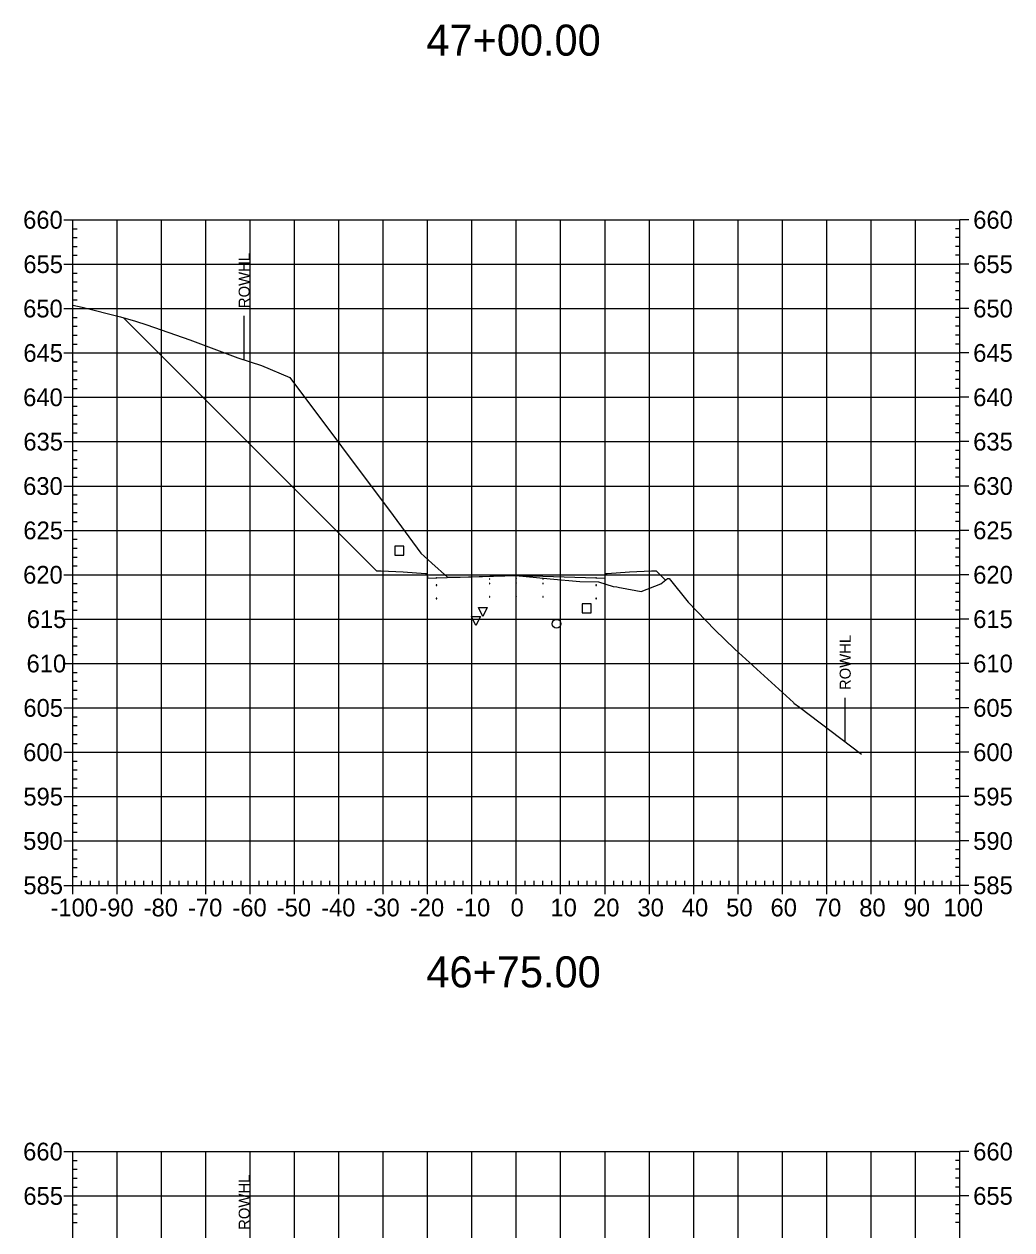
# Model space of a CAD drawing. Extents: x 708103 to 717568, y 374476 to 378707.
# Drawn here: x 712241 to 712463.7, y 377347 to 377618.7 of the extents above; entities that cross this region are included whole.
import ezdxf

# ---------------------------------------------------------------- set-up
doc = ezdxf.new("R2010")
doc.units = 0
for name, color, linetype in [('1', 7, 'Continuous'), ('10', 7, 'Continuous'), ('13', 7, 'Continuous'), ('14', 7, 'Continuous'), ('22', 7, 'Continuous'), ('4', 7, 'Continuous'), ('57', 7, 'Continuous'), ('Existing', 7, 'Continuous'), ('XS_Right_of_Way', 7, 'Continuous')]:
    doc.layers.add(name, color=color, linetype=linetype)

msp = doc.modelspace()

# ---------------------------------------------------------------- linework, layer by layer
for points in [[(712333.93, 377492.24), (712334.03, 377492.24), (712334.03, 377492.34), (712333.93, 377492.34)], [(712345.93, 377493.6), (712346.03, 377493.6), (712346.03, 377493.7), (712345.93, 377493.7)], [(712345.93, 377492.6), (712346.03, 377492.6), (712346.03, 377492.7), (712345.93, 377492.7)], [(712351.93, 377493.72), (712352.03, 377493.72), (712352.03, 377493.82), (712351.93, 377493.82)], [(712351.93, 377492.72), (712352.03, 377492.72), (712352.03, 377492.82), (712351.93, 377492.82)], [(712357.93, 377493.6), (712358.03, 377493.6), (712358.03, 377493.7), (712357.93, 377493.7)], [(712357.93, 377492.6), (712358.03, 377492.6), (712358.03, 377492.7), (712357.93, 377492.7)], [(712369.93, 377492.24), (712370.03, 377492.24), (712370.03, 377492.34), (712369.93, 377492.34)], [(712345.93, 377489.6), (712346.03, 377489.6), (712346.03, 377489.7), (712345.93, 377489.7)], [(712351.93, 377489.72), (712352.03, 377489.72), (712352.03, 377489.82), (712351.93, 377489.82)], [(712357.93, 377489.6), (712358.03, 377489.6), (712358.03, 377489.7), (712357.93, 377489.7)], [(712333.93, 377489.24), (712334.03, 377489.24), (712334.03, 377489.34), (712333.93, 377489.34)], [(712369.93, 377489.24), (712370.03, 377489.24), (712370.03, 377489.34), (712369.93, 377489.34)]]:
    msp.add_lwpolyline(points, close=True)
at = {"layer": '1'}
for points in [[(712344.45, 377485.25), (712343.45, 377487.25), (712345.45, 377487.25)], [(712342.88, 377483.21), (712341.88, 377485.21), (712343.88, 377485.21)]]:
    msp.add_lwpolyline(points, close=True, dxfattribs=at)
at = {"layer": '10'}
msp.add_lwpolyline([(712324.59, 377499.07), (712326.59, 377499.07), (712326.59, 377501.07), (712324.59, 377501.07)], close=True, dxfattribs=at)
at = {"layer": '13'}
msp.add_circle((712361.05, 377483.58), 1, dxfattribs=at)
at = {"layer": '14'}
for points in [[(712263.46, 377552.54), (712263.46, 377552.59), (712263.46, 377552.54), (712263.41, 377552.54), (712263.46, 377552.54), (712263.46, 377552.49), (712263.46, 377552.54), (712263.51, 377552.54)], [(712333.98, 377493.96), (712333.98, 377494.01), (712333.98, 377493.96), (712333.93, 377493.96), (712333.98, 377493.96), (712333.98, 377493.91), (712333.98, 377493.96), (712334.03, 377493.96)], [(712351.98, 377494.44), (712351.98, 377494.49), (712351.98, 377494.44), (712351.93, 377494.44), (712351.98, 377494.44), (712351.98, 377494.39), (712351.98, 377494.44), (712352.03, 377494.44)], [(712369.98, 377493.96), (712369.98, 377494.01), (712369.98, 377493.96), (712369.93, 377493.96), (712369.98, 377493.96), (712369.98, 377493.91), (712369.98, 377493.96), (712370.03, 377493.96)], [(712385.6, 377493.4), (712385.6, 377493.45), (712385.6, 377493.4), (712385.55, 377493.4), (712385.6, 377493.4), (712385.6, 377493.35), (712385.6, 377493.4), (712385.65, 377493.4)]]:
    msp.add_lwpolyline(points, dxfattribs=at)
at = {"layer": '22'}
msp.add_lwpolyline([(712263.46, 377552.54), (712320.48, 377495.52), (712321.48, 377495.48), (712326.48, 377495.28), (712331.48, 377494.88), (712331.9, 377494.88), (712331.98, 377493.88), (712333.98, 377493.96), (712345.98, 377494.32), (712351.98, 377494.44), (712357.98, 377494.32), (712369.98, 377493.96), (712371.98, 377493.88), (712372.07, 377494.88), (712372.48, 377494.88), (712377.48, 377495.28), (712382.48, 377495.48), (712383.48, 377495.52), (712385.6, 377493.4)], dxfattribs=at)
at = {"layer": '4'}
msp.add_lwpolyline([(712366.85, 377486.07), (712368.85, 377486.07), (712368.85, 377488.07), (712366.85, 377488.07)], close=True, dxfattribs=at)
at = {"layer": '57'}
for p, q in [((712249.98, 377574.63), (712251.98, 377574.63)), ((712251.98, 377574.63), (712451.98, 377574.63)), ((712251.98, 377424.63), (712251.98, 377574.63)), ((712251.98, 377424.63), (712251.98, 377574.63)), ((712261.98, 377424.63), (712261.98, 377574.63)), ((712271.98, 377424.63), (712271.98, 377574.63)), ((712281.98, 377424.63), (712281.98, 377574.63)), ((712291.98, 377424.63), (712291.98, 377574.63)), ((712301.98, 377424.63), (712301.98, 377574.63)), ((712311.98, 377424.63), (712311.98, 377574.63)), ((712321.98, 377424.63), (712321.98, 377574.63)), ((712331.98, 377424.63), (712331.98, 377574.63)), ((712341.98, 377424.63), (712341.98, 377574.63)), ((712351.98, 377424.63), (712351.98, 377574.63)), ((712361.98, 377424.63), (712361.98, 377574.63)), ((712371.98, 377424.63), (712371.98, 377574.63)), ((712381.98, 377424.63), (712381.98, 377574.63)), ((712391.98, 377424.63), (712391.98, 377574.63)), ((712401.98, 377424.63), (712401.98, 377574.63)), ((712411.98, 377424.63), (712411.98, 377574.63)), ((712421.98, 377424.63), (712421.98, 377574.63)), ((712431.98, 377424.63), (712431.98, 377574.63)), ((712441.98, 377424.63), (712441.98, 377574.63)), ((712451.98, 377424.63), (712451.98, 377574.63)), ((712451.98, 377424.63), (712451.98, 377574.63)), ((712453.98, 377574.63), (712451.98, 377574.63)), ((712251.98, 377572.63), (712252.98, 377572.63)), ((712451.98, 377572.63), (712450.98, 377572.63)), ((712251.98, 377570.63), (712252.98, 377570.63)), ((712251.98, 377568.63), (712252.98, 377568.63)), ((712451.98, 377570.63), (712450.98, 377570.63)), ((712451.98, 377568.63), (712450.98, 377568.63)), ((712251.98, 377566.63), (712252.98, 377566.63)), ((712451.98, 377566.63), (712450.98, 377566.63)), ((712249.98, 377564.63), (712251.98, 377564.63)), ((712251.98, 377564.63), (712451.98, 377564.63)), ((712453.98, 377564.63), (712451.98, 377564.63)), ((712251.98, 377562.63), (712252.98, 377562.63)), ((712251.98, 377560.63), (712252.98, 377560.63)), ((712451.98, 377562.63), (712450.98, 377562.63)), ((712451.98, 377560.63), (712450.98, 377560.63)), ((712251.98, 377558.63), (712252.98, 377558.63)), ((712451.98, 377558.63), (712450.98, 377558.63)), ((712251.98, 377556.63), (712252.98, 377556.63)), ((712451.98, 377556.63), (712450.98, 377556.63)), ((712249.98, 377554.63), (712251.98, 377554.63)), ((712251.98, 377554.63), (712451.98, 377554.63)), ((712251.98, 377552.63), (712252.98, 377552.63)), ((712451.98, 377552.63), (712450.98, 377552.63)), ((712453.98, 377554.63), (712451.98, 377554.63)), ((712251.98, 377550.63), (712252.98, 377550.63)), ((712451.98, 377550.63), (712450.98, 377550.63)), ((712251.98, 377548.63), (712252.98, 377548.63)), ((712251.98, 377546.63), (712252.98, 377546.63)), ((712451.98, 377548.63), (712450.98, 377548.63)), ((712451.98, 377546.63), (712450.98, 377546.63)), ((712249.98, 377544.63), (712251.98, 377544.63)), ((712251.98, 377544.63), (712451.98, 377544.63)), ((712453.98, 377544.63), (712451.98, 377544.63)), ((712251.98, 377542.63), (712252.98, 377542.63)), ((712451.98, 377542.63), (712450.98, 377542.63)), ((712251.98, 377540.63), (712252.98, 377540.63)), ((712251.98, 377538.63), (712252.98, 377538.63)), ((712451.98, 377540.63), (712450.98, 377540.63)), ((712451.98, 377538.63), (712450.98, 377538.63)), ((712251.98, 377536.63), (712252.98, 377536.63)), ((712451.98, 377536.63), (712450.98, 377536.63)), ((712249.98, 377534.63), (712251.98, 377534.63)), ((712251.98, 377534.63), (712451.98, 377534.63)), ((712453.98, 377534.63), (712451.98, 377534.63)), ((712251.98, 377532.63), (712252.98, 377532.63)), ((712251.98, 377530.63), (712252.98, 377530.63)), ((712451.98, 377532.63), (712450.98, 377532.63)), ((712451.98, 377530.63), (712450.98, 377530.63)), ((712251.98, 377528.63), (712252.98, 377528.63)), ((712451.98, 377528.63), (712450.98, 377528.63)), ((712251.98, 377526.63), (712252.98, 377526.63)), ((712451.98, 377526.63), (712450.98, 377526.63)), ((712249.98, 377524.63), (712251.98, 377524.63)), ((712251.98, 377524.63), (712451.98, 377524.63)), ((712251.98, 377522.63), (712252.98, 377522.63)), ((712451.98, 377522.63), (712450.98, 377522.63)), ((712453.98, 377524.63), (712451.98, 377524.63)), ((712251.98, 377520.63), (712252.98, 377520.63)), ((712451.98, 377520.63), (712450.98, 377520.63)), ((712251.98, 377518.63), (712252.98, 377518.63)), ((712451.98, 377518.63), (712450.98, 377518.63)), ((712249.98, 377514.63), (712251.98, 377514.63)), ((712251.98, 377516.63), (712252.98, 377516.63)), ((712251.98, 377514.63), (712451.98, 377514.63)), ((712451.98, 377516.63), (712450.98, 377516.63)), ((712453.98, 377514.63), (712451.98, 377514.63)), ((712251.98, 377512.63), (712252.98, 377512.63)), ((712451.98, 377512.63), (712450.98, 377512.63)), ((712251.98, 377510.63), (712252.98, 377510.63)), ((712251.98, 377508.63), (712252.98, 377508.63)), ((712451.98, 377510.63), (712450.98, 377510.63)), ((712451.98, 377508.63), (712450.98, 377508.63)), ((712251.98, 377506.63), (712252.98, 377506.63)), ((712451.98, 377506.63), (712450.98, 377506.63)), ((712249.98, 377504.63), (712251.98, 377504.63)), ((712251.98, 377504.63), (712451.98, 377504.63)), ((712453.98, 377504.63), (712451.98, 377504.63)), ((712251.98, 377502.63), (712252.98, 377502.63)), ((712251.98, 377500.63), (712252.98, 377500.63)), ((712451.98, 377502.63), (712450.98, 377502.63)), ((712451.98, 377500.63), (712450.98, 377500.63)), ((712251.98, 377498.63), (712252.98, 377498.63)), ((712451.98, 377498.63), (712450.98, 377498.63)), ((712251.98, 377496.63), (712252.98, 377496.63)), ((712451.98, 377496.63), (712450.98, 377496.63)), ((712249.98, 377494.63), (712251.98, 377494.63)), ((712251.98, 377494.63), (712451.98, 377494.63)), ((712251.98, 377492.63), (712252.98, 377492.63)), ((712451.98, 377492.63), (712450.98, 377492.63)), ((712453.98, 377494.63), (712451.98, 377494.63)), ((712251.98, 377490.63), (712252.98, 377490.63)), ((712451.98, 377490.63), (712450.98, 377490.63)), ((712251.98, 377488.63), (712252.98, 377488.63)), ((712451.98, 377488.63), (712450.98, 377488.63)), ((712249.98, 377484.63), (712251.98, 377484.63)), ((712251.98, 377486.63), (712252.98, 377486.63)), ((712251.98, 377484.63), (712451.98, 377484.63)), ((712451.98, 377486.63), (712450.98, 377486.63)), ((712453.98, 377484.63), (712451.98, 377484.63)), ((712251.98, 377482.63), (712252.98, 377482.63)), ((712451.98, 377482.63), (712450.98, 377482.63)), ((712251.98, 377480.63), (712252.98, 377480.63)), ((712251.98, 377478.63), (712252.98, 377478.63)), ((712451.98, 377480.63), (712450.98, 377480.63)), ((712451.98, 377478.63), (712450.98, 377478.63)), ((712251.98, 377476.63), (712252.98, 377476.63)), ((712451.98, 377476.63), (712450.98, 377476.63)), ((712249.98, 377474.63), (712251.98, 377474.63)), ((712251.98, 377474.63), (712451.98, 377474.63)), ((712453.98, 377474.63), (712451.98, 377474.63)), ((712251.98, 377472.63), (712252.98, 377472.63)), ((712251.98, 377470.63), (712252.98, 377470.63)), ((712451.98, 377472.63), (712450.98, 377472.63)), ((712451.98, 377470.63), (712450.98, 377470.63)), ((712251.98, 377468.63), (712252.98, 377468.63)), ((712451.98, 377468.63), (712450.98, 377468.63)), ((712251.98, 377466.63), (712252.98, 377466.63)), ((712451.98, 377466.63), (712450.98, 377466.63)), ((712249.98, 377464.63), (712251.98, 377464.63)), ((712251.98, 377464.63), (712451.98, 377464.63)), ((712251.98, 377462.63), (712252.98, 377462.63)), ((712451.98, 377462.63), (712450.98, 377462.63)), ((712453.98, 377464.63), (712451.98, 377464.63)), ((712251.98, 377460.63), (712252.98, 377460.63)), ((712451.98, 377460.63), (712450.98, 377460.63)), ((712251.98, 377458.63), (712252.98, 377458.63)), ((712451.98, 377458.63), (712450.98, 377458.63)), ((712249.98, 377454.63), (712251.98, 377454.63)), ((712251.98, 377456.63), (712252.98, 377456.63)), ((712251.98, 377454.63), (712451.98, 377454.63)), ((712451.98, 377456.63), (712450.98, 377456.63)), ((712453.98, 377454.63), (712451.98, 377454.63)), ((712251.98, 377452.63), (712252.98, 377452.63)), ((712451.98, 377452.63), (712450.98, 377452.63)), ((712251.98, 377450.63), (712252.98, 377450.63)), ((712451.98, 377450.63), (712450.98, 377450.63)), ((712251.98, 377448.63), (712252.98, 377448.63)), ((712251.98, 377446.63), (712252.98, 377446.63)), ((712451.98, 377448.63), (712450.98, 377448.63)), ((712451.98, 377446.63), (712450.98, 377446.63)), ((712249.98, 377444.63), (712251.98, 377444.63)), ((712251.98, 377444.63), (712451.98, 377444.63)), ((712453.98, 377444.63), (712451.98, 377444.63)), ((712251.98, 377442.63), (712252.98, 377442.63)), ((712251.98, 377440.63), (712252.98, 377440.63)), ((712451.98, 377442.63), (712450.98, 377442.63)), ((712451.98, 377440.63), (712450.98, 377440.63)), ((712251.98, 377438.63), (712252.98, 377438.63)), ((712451.98, 377438.63), (712450.98, 377438.63)), ((712251.98, 377436.63), (712252.98, 377436.63)), ((712451.98, 377436.63), (712450.98, 377436.63)), ((712249.98, 377434.63), (712251.98, 377434.63)), ((712251.98, 377434.63), (712451.98, 377434.63)), ((712251.98, 377432.63), (712252.98, 377432.63)), ((712451.98, 377432.63), (712450.98, 377432.63)), ((712453.98, 377434.63), (712451.98, 377434.63)), ((712251.98, 377430.63), (712252.98, 377430.63)), ((712451.98, 377430.63), (712450.98, 377430.63)), ((712251.98, 377428.63), (712252.98, 377428.63)), ((712451.98, 377428.63), (712450.98, 377428.63)), ((712249.98, 377424.63), (712251.98, 377424.63)), ((712251.98, 377426.63), (712252.98, 377426.63)), ((712251.98, 377424.63), (712451.98, 377424.63)), ((712251.98, 377424.63), (712451.98, 377424.63)), ((712251.98, 377422.63), (712251.98, 377424.63)), ((712253.98, 377424.63), (712253.98, 377425.63)), ((712255.98, 377424.63), (712255.98, 377425.63)), ((712257.98, 377424.63), (712257.98, 377425.63)), ((712259.98, 377424.63), (712259.98, 377425.63)), ((712261.98, 377422.63), (712261.98, 377424.63)), ((712263.98, 377424.63), (712263.98, 377425.63)), ((712265.98, 377424.63), (712265.98, 377425.63)), ((712267.98, 377424.63), (712267.98, 377425.63)), ((712269.98, 377424.63), (712269.98, 377425.63)), ((712271.98, 377422.63), (712271.98, 377424.63)), ((712273.98, 377424.63), (712273.98, 377425.63)), ((712275.98, 377424.63), (712275.98, 377425.63)), ((712277.98, 377424.63), (712277.98, 377425.63)), ((712279.98, 377424.63), (712279.98, 377425.63)), ((712281.98, 377422.63), (712281.98, 377424.63)), ((712283.98, 377424.63), (712283.98, 377425.63)), ((712285.98, 377424.63), (712285.98, 377425.63)), ((712287.98, 377424.63), (712287.98, 377425.63)), ((712289.98, 377424.63), (712289.98, 377425.63)), ((712291.98, 377422.63), (712291.98, 377424.63)), ((712293.98, 377424.63), (712293.98, 377425.63)), ((712295.98, 377424.63), (712295.98, 377425.63)), ((712297.98, 377424.63), (712297.98, 377425.63)), ((712299.98, 377424.63), (712299.98, 377425.63)), ((712301.98, 377422.63), (712301.98, 377424.63)), ((712303.98, 377424.63), (712303.98, 377425.63)), ((712305.98, 377424.63), (712305.98, 377425.63)), ((712307.98, 377424.63), (712307.98, 377425.63)), ((712309.98, 377424.63), (712309.98, 377425.63)), ((712311.98, 377422.63), (712311.98, 377424.63)), ((712313.98, 377424.63), (712313.98, 377425.63)), ((712315.98, 377424.63), (712315.98, 377425.63)), ((712317.98, 377424.63), (712317.98, 377425.63)), ((712319.98, 377424.63), (712319.98, 377425.63)), ((712321.98, 377422.63), (712321.98, 377424.63)), ((712323.98, 377424.63), (712323.98, 377425.63)), ((712325.98, 377424.63), (712325.98, 377425.63)), ((712327.98, 377424.63), (712327.98, 377425.63)), ((712329.98, 377424.63), (712329.98, 377425.63)), ((712331.98, 377422.63), (712331.98, 377424.63)), ((712333.98, 377424.63), (712333.98, 377425.63)), ((712335.98, 377424.63), (712335.98, 377425.63)), ((712337.98, 377424.63), (712337.98, 377425.63)), ((712339.98, 377424.63), (712339.98, 377425.63)), ((712341.98, 377422.63), (712341.98, 377424.63)), ((712343.98, 377424.63), (712343.98, 377425.63)), ((712345.98, 377424.63), (712345.98, 377425.63)), ((712347.98, 377424.63), (712347.98, 377425.63)), ((712349.98, 377424.63), (712349.98, 377425.63)), ((712351.98, 377422.63), (712351.98, 377424.63)), ((712353.98, 377424.63), (712353.98, 377425.63)), ((712355.98, 377424.63), (712355.98, 377425.63)), ((712357.98, 377424.63), (712357.98, 377425.63)), ((712359.98, 377424.63), (712359.98, 377425.63)), ((712361.98, 377422.63), (712361.98, 377424.63)), ((712363.98, 377424.63), (712363.98, 377425.63)), ((712365.98, 377424.63), (712365.98, 377425.63)), ((712367.98, 377424.63), (712367.98, 377425.63)), ((712369.98, 377424.63), (712369.98, 377425.63)), ((712371.98, 377422.63), (712371.98, 377424.63)), ((712373.98, 377424.63), (712373.98, 377425.63)), ((712375.98, 377424.63), (712375.98, 377425.63)), ((712377.98, 377424.63), (712377.98, 377425.63)), ((712379.98, 377424.63), (712379.98, 377425.63)), ((712381.98, 377422.63), (712381.98, 377424.63)), ((712383.98, 377424.63), (712383.98, 377425.63)), ((712385.98, 377424.63), (712385.98, 377425.63)), ((712387.98, 377424.63), (712387.98, 377425.63)), ((712389.98, 377424.63), (712389.98, 377425.63)), ((712391.98, 377422.63), (712391.98, 377424.63)), ((712393.98, 377424.63), (712393.98, 377425.63)), ((712395.98, 377424.63), (712395.98, 377425.63)), ((712397.98, 377424.63), (712397.98, 377425.63)), ((712399.98, 377424.63), (712399.98, 377425.63)), ((712401.98, 377422.63), (712401.98, 377424.63)), ((712403.98, 377424.63), (712403.98, 377425.63)), ((712405.98, 377424.63), (712405.98, 377425.63)), ((712407.98, 377424.63), (712407.98, 377425.63)), ((712409.98, 377424.63), (712409.98, 377425.63)), ((712411.98, 377422.63), (712411.98, 377424.63)), ((712413.98, 377424.63), (712413.98, 377425.63)), ((712415.98, 377424.63), (712415.98, 377425.63)), ((712417.98, 377424.63), (712417.98, 377425.63)), ((712419.98, 377424.63), (712419.98, 377425.63)), ((712421.98, 377422.63), (712421.98, 377424.63)), ((712423.98, 377424.63), (712423.98, 377425.63)), ((712425.98, 377424.63), (712425.98, 377425.63)), ((712427.98, 377424.63), (712427.98, 377425.63)), ((712429.98, 377424.63), (712429.98, 377425.63)), ((712431.98, 377422.63), (712431.98, 377424.63)), ((712433.98, 377424.63), (712433.98, 377425.63)), ((712435.98, 377424.63), (712435.98, 377425.63)), ((712437.98, 377424.63), (712437.98, 377425.63)), ((712439.98, 377424.63), (712439.98, 377425.63)), ((712441.98, 377422.63), (712441.98, 377424.63)), ((712443.98, 377424.63), (712443.98, 377425.63)), ((712445.98, 377424.63), (712445.98, 377425.63)), ((712447.98, 377424.63), (712447.98, 377425.63)), ((712449.98, 377424.63), (712449.98, 377425.63)), ((712451.98, 377426.63), (712450.98, 377426.63)), ((712451.98, 377422.63), (712451.98, 377424.63)), ((712453.98, 377424.63), (712451.98, 377424.63)), ((712249.98, 377364.63), (712251.98, 377364.63)), ((712251.98, 377364.63), (712451.98, 377364.63)), ((712251.98, 377224.63), (712251.98, 377364.63)), ((712251.98, 377224.63), (712251.98, 377364.63)), ((712261.98, 377224.63), (712261.98, 377364.63)), ((712271.98, 377224.63), (712271.98, 377364.63)), ((712281.98, 377224.63), (712281.98, 377364.63)), ((712291.98, 377224.63), (712291.98, 377364.63)), ((712301.98, 377224.63), (712301.98, 377364.63)), ((712311.98, 377224.63), (712311.98, 377364.63)), ((712321.98, 377224.63), (712321.98, 377364.63)), ((712331.98, 377224.63), (712331.98, 377364.63)), ((712341.98, 377224.63), (712341.98, 377364.63)), ((712351.98, 377224.63), (712351.98, 377364.63)), ((712361.98, 377224.63), (712361.98, 377364.63)), ((712371.98, 377224.63), (712371.98, 377364.63)), ((712381.98, 377224.63), (712381.98, 377364.63)), ((712391.98, 377224.63), (712391.98, 377364.63)), ((712401.98, 377224.63), (712401.98, 377364.63)), ((712411.98, 377224.63), (712411.98, 377364.63)), ((712421.98, 377224.63), (712421.98, 377364.63)), ((712431.98, 377224.63), (712431.98, 377364.63)), ((712441.98, 377224.63), (712441.98, 377364.63)), ((712451.98, 377224.63), (712451.98, 377364.63)), ((712451.98, 377224.63), (712451.98, 377364.63)), ((712453.98, 377364.63), (712451.98, 377364.63)), ((712251.98, 377362.63), (712252.98, 377362.63)), ((712451.98, 377362.63), (712450.98, 377362.63)), ((712251.98, 377360.63), (712252.98, 377360.63)), ((712451.98, 377360.63), (712450.98, 377360.63)), ((712251.98, 377358.63), (712252.98, 377358.63)), ((712251.98, 377356.63), (712252.98, 377356.63)), ((712451.98, 377358.63), (712450.98, 377358.63)), ((712451.98, 377356.63), (712450.98, 377356.63)), ((712249.98, 377354.63), (712251.98, 377354.63)), ((712251.98, 377354.63), (712451.98, 377354.63)), ((712453.98, 377354.63), (712451.98, 377354.63)), ((712251.98, 377352.63), (712252.98, 377352.63)), ((712451.98, 377352.63), (712450.98, 377352.63)), ((712251.98, 377350.63), (712252.98, 377350.63)), ((712251.98, 377348.63), (712252.98, 377348.63)), ((712451.98, 377350.63), (712450.98, 377350.63)), ((712451.98, 377348.63), (712450.98, 377348.63))]:
    msp.add_line(p, q, dxfattribs=at)
at = {"layer": 'Existing'}
msp.add_lwpolyline([(712251.98, 377555.43), (712254.12, 377554.91), (712262.73, 377552.74), (712266.16, 377551.8), (712268.72, 377550.99), (712278.4, 377547.58), (712289.18, 377543.56), (712294.55, 377541.78), (712300.9, 377539.06), (712324.19, 377507.95), (712330.45, 377499.51), (712332.97, 377497.22), (712336.44, 377494.1), (712339.34, 377494.11), (712351.9, 377494.45), (712359.62, 377493.7), (712366.27, 377493.11), (712370.53, 377493), (712373.84, 377491.95), (712374.68, 377491.89), (712375.22, 377491.73), (712375.66, 377491.65), (712380.16, 377490.87), (712384.57, 377492.56), (712386.05, 377493.76), (712386.42, 377493.82), (712390.75, 377488.42), (712396.72, 377482.23), (712401.25, 377477.87), (712414.44, 377465.83), (712414.56, 377465.71), (712415.81, 377464.76), (712429.82, 377454.18)], dxfattribs=at)
at = {"layer": 'XS_Right_of_Way'}
for p, q in [((712290.57, 377552.96), (712290.57, 377542.96)), ((712426.05, 377466.89), (712426.05, 377456.89))]:
    msp.add_line(p, q, dxfattribs=at)

# ---------------------------------------------------------------- texts
at = {"layer": '1'}
for s, p in [('47+00.00', (712331.71, 377611.63)), ('46+75.00', (712331.71, 377401.63))]:
    msp.add_text(s, height=7, dxfattribs=at).set_placement(p)
at = {"layer": '14'}
for p in [(712321.45, 377495.43), (712382.45, 377495.43), (712321.45, 377494.76), (712326.45, 377494.56), (712377.45, 377494.56), (712382.45, 377494.76)]:
    msp.add_text('+', height=0.1, dxfattribs=at).set_placement(p)
at = {"layer": '57'}
for s, p in [('660', (712240.81, 377572.63)), ('660', (712454.98, 377572.63)), ('655', (712240.86, 377562.63)), ('655', (712454.98, 377562.63)), ('650', (712240.81, 377552.63)), ('650', (712454.98, 377552.63)), ('645', (712240.86, 377542.63)), ('645', (712454.98, 377542.63)), ('640', (712240.81, 377532.63)), ('640', (712454.98, 377532.63)), ('635', (712240.86, 377522.63)), ('635', (712454.98, 377522.63)), ('630', (712240.81, 377512.63)), ('630', (712454.98, 377512.63)), ('625', (712240.86, 377502.63)), ('625', (712454.98, 377502.63)), ('620', (712240.81, 377492.63)), ('620', (712454.98, 377492.63)), ('615', (712241.63, 377482.63)), ('615', (712454.98, 377482.63)), ('610', (712241.58, 377472.63)), ('610', (712454.98, 377472.63)), ('605', (712240.86, 377462.63)), ('605', (712454.98, 377462.63)), ('600', (712240.81, 377452.63)), ('600', (712454.98, 377452.63)), ('595', (712240.86, 377442.63)), ('595', (712454.98, 377442.63)), ('590', (712240.81, 377432.63)), ('590', (712454.98, 377432.63)), ('585', (712240.86, 377422.63)), ('585', (712454.98, 377422.63)), ('-100', (712246.97, 377417.63)), ('-90', (712257.98, 377417.63)), ('-80', (712267.98, 377417.63)), ('-70', (712277.98, 377417.63)), ('-60', (712287.98, 377417.63)), ('-50', (712297.98, 377417.63)), ('-40', (712307.98, 377417.63)), ('-30', (712317.98, 377417.63)), ('-20', (712327.98, 377417.63)), ('-10', (712338.37, 377417.63)), ('0', (712350.69, 377417.63)), ('10', (712359.68, 377417.63)), ('20', (712369.29, 377417.63)), ('30', (712379.29, 377417.63)), ('40', (712389.29, 377417.63)), ('50', (712399.29, 377417.63)), ('60', (712409.29, 377417.63)), ('70', (712419.29, 377417.63)), ('80', (712429.29, 377417.63)), ('90', (712439.29, 377417.63)), ('100', (712448.28, 377417.63)), ('660', (712240.81, 377362.63)), ('660', (712454.98, 377362.63)), ('655', (712240.86, 377352.63)), ('655', (712454.98, 377352.63))]:
    msp.add_text(s, height=4, dxfattribs=at).set_placement(p)
at = {"layer": 'XS_Right_of_Way'}
for p in [(712291.89, 377554.72), (712427.37, 377468.65), (712291.9, 377346.98)]:
    msp.add_text('ROWHL', height=2.5, rotation=90, dxfattribs=at).set_placement(p)

doc.saveas('drawing.dxf')
